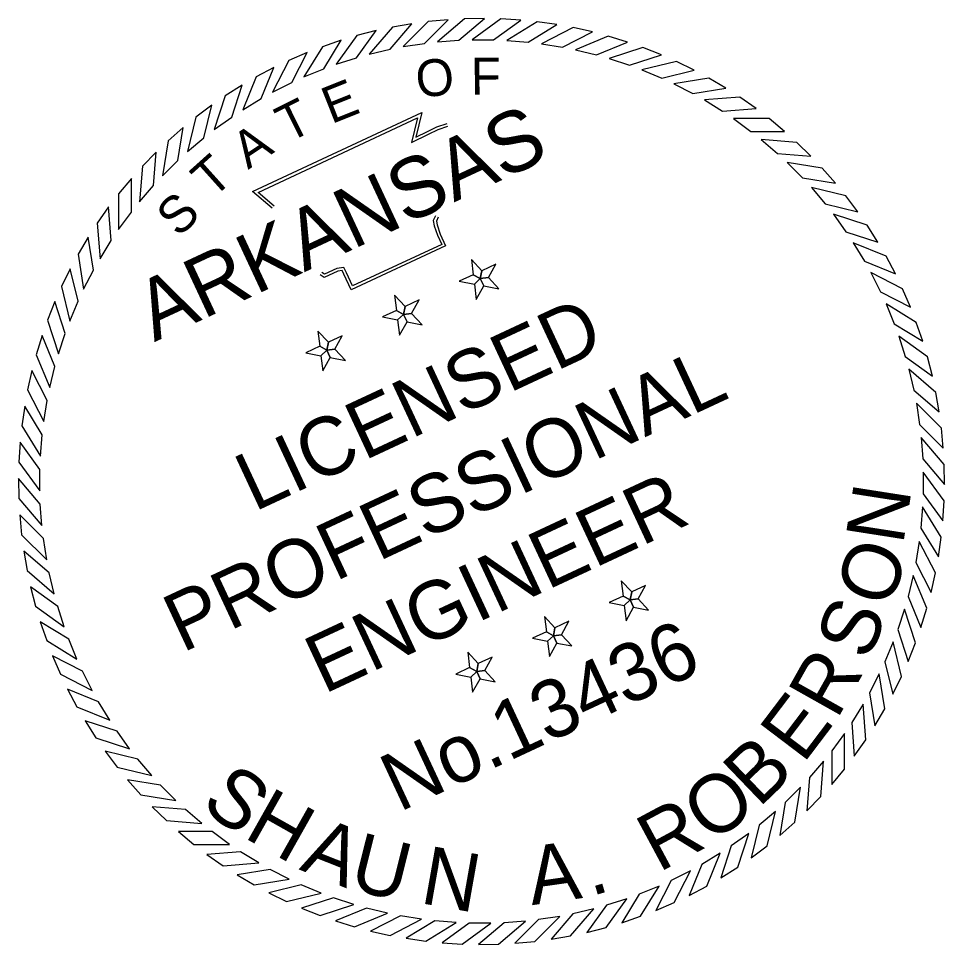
# Model space of a CAD drawing. Extents: x 756658 to 763719, y 1656413 to 1661090.
# Drawn here: x 759296.9 to 759535.5, y 1659245.9 to 1659484.6 of the extents above; entities that cross this region are included whole.
import ezdxf

# ---------------------------------------------------------------- set-up
doc = ezdxf.new("R2010")
doc.units = 0
doc.layers.add('G-ANNO-SYMB', color=7, linetype='Continuous')

msp = doc.modelspace()

# ---------------------------------------------------------------- linework, layer by layer
at = {"layer": 'G-ANNO-SYMB'}
for points in [[(759416.93, 1659484.58), (759411.8, 1659484.5), (759404.85, 1659478.56), (759410.37, 1659478.98)], [(759398.26, 1659483.23), (759393.2, 1659482.35), (759387.26, 1659475.4), (759392.66, 1659476.67)], [(759407.57, 1659484.27), (759402.46, 1659483.79), (759395.99, 1659477.33), (759401.47, 1659478.18)], [(759426.29, 1659484.16), (759421.17, 1659484.48), (759413.77, 1659479.1), (759419.31, 1659479.09)], [(759435.59, 1659483), (759430.51, 1659483.72), (759422.71, 1659478.94), (759428.24, 1659478.49)], [(759444.76, 1659481.11), (759439.76, 1659482.23), (759431.61, 1659478.08), (759437.08, 1659477.19)], [(759389.06, 1659481.46), (759384.09, 1659480.19), (759378.71, 1659472.79), (759383.99, 1659474.49)], [(759453.77, 1659478.51), (759448.86, 1659480.02), (759440.41, 1659476.52), (759445.8, 1659475.21)], [(759380.02, 1659478.98), (759375.17, 1659477.32), (759370.39, 1659469.52), (759375.52, 1659471.62)], [(759371.21, 1659475.79), (759366.5, 1659473.75), (759362.35, 1659465.6), (759367.3, 1659468.11)], [(759462.53, 1659475.21), (759457.76, 1659477.1), (759449.07, 1659474.28), (759454.33, 1659472.55)], [(759471.02, 1659471.24), (759466.41, 1659473.49), (759457.52, 1659471.36), (759462.63, 1659469.22)], [(759362.68, 1659471.92), (759358.14, 1659469.52), (759354.65, 1659461.07), (759359.38, 1659463.95)], [(759479.16, 1659466.61), (759474.75, 1659469.22), (759465.72, 1659467.79), (759470.65, 1659465.26)], [(759354.48, 1659467.39), (759350.14, 1659464.65), (759347.32, 1659455.95), (759351.81, 1659459.19)], [(759486.92, 1659461.35), (759482.72, 1659464.3), (759473.61, 1659463.59), (759478.32, 1659460.67)], [(759346.65, 1659462.24), (759342.55, 1659459.16), (759340.42, 1659450.27), (759344.64, 1659453.85)], [(759494.24, 1659455.5), (759490.29, 1659458.78), (759481.14, 1659458.78), (759485.62, 1659455.5)], [(759339.26, 1659456.48), (759335.41, 1659453.09), (759333.98, 1659444.06), (759337.91, 1659447.97)], [(759501.08, 1659449.1), (759497.4, 1659452.67), (759488.28, 1659453.39), (759492.48, 1659449.78)], [(759332.34, 1659450.17), (759328.77, 1659446.49), (759328.05, 1659437.37), (759331.66, 1659441.57)], [(759507.4, 1659442.18), (759504, 1659446.03), (759494.97, 1659447.46), (759498.88, 1659443.53)], [(759325.94, 1659443.33), (759322.67, 1659439.38), (759322.67, 1659430.23), (759325.94, 1659434.71)], [(759513.15, 1659434.79), (759510.07, 1659438.89), (759501.18, 1659441.03), (759504.76, 1659436.8)], [(759320.09, 1659436.01), (759317.14, 1659431.81), (759317.86, 1659422.69), (759320.77, 1659427.41)], [(759518.31, 1659426.97), (759515.56, 1659431.3), (759506.86, 1659434.13), (759510.1, 1659429.63)], [(759314.84, 1659428.25), (759312.22, 1659423.84), (759313.65, 1659414.8), (759316.19, 1659419.73)], [(759522.83, 1659418.76), (759520.43, 1659423.3), (759511.98, 1659426.8), (759514.86, 1659422.06)], [(759415.87, 1659417.55), (759416.27, 1659419.59), (759413.57, 1659422.49), (759414.05, 1659418.56)], [(759310.21, 1659420.11), (759307.95, 1659415.5), (759310.08, 1659406.61), (759312.22, 1659411.72)], [(759415.87, 1659417.55), (759417.94, 1659417.8), (759419.86, 1659421.27), (759416.27, 1659419.59)], [(759415.87, 1659417.55), (759414.05, 1659418.56), (759410.46, 1659416.88), (759414.35, 1659416.13)], [(759415.87, 1659417.55), (759416.75, 1659415.66), (759420.64, 1659414.9), (759417.94, 1659417.8)], [(759526.7, 1659410.23), (759524.66, 1659414.94), (759516.52, 1659419.09), (759519.02, 1659414.14)], [(759415.87, 1659417.55), (759414.35, 1659416.13), (759414.83, 1659412.19), (759416.75, 1659415.66)], [(759396.1, 1659408.33), (759396.49, 1659410.37), (759393.79, 1659413.27), (759394.28, 1659409.34)], [(759306.23, 1659411.62), (759304.34, 1659406.85), (759307.17, 1659398.16), (759308.9, 1659403.42)], [(759396.1, 1659408.33), (759398.17, 1659408.58), (759400.09, 1659412.05), (759396.49, 1659410.37)], [(759529.89, 1659401.42), (759528.23, 1659406.27), (759520.43, 1659411.05), (759522.53, 1659405.92)], [(759396.1, 1659408.33), (759394.28, 1659409.34), (759390.68, 1659407.66), (759394.57, 1659406.91)], [(759396.1, 1659408.33), (759394.57, 1659406.91), (759395.06, 1659402.97), (759396.98, 1659406.44)], [(759396.1, 1659408.33), (759396.98, 1659406.44), (759400.87, 1659405.68), (759398.17, 1659408.58)], [(759376.32, 1659399.11), (759376.72, 1659401.15), (759374.02, 1659404.05), (759374.5, 1659400.12)], [(759302.93, 1659402.85), (759301.42, 1659397.95), (759304.92, 1659389.5), (759306.23, 1659394.89)], [(759376.32, 1659399.11), (759378.39, 1659399.36), (759380.31, 1659402.83), (759376.72, 1659401.15)], [(759532.37, 1659392.39), (759531.1, 1659397.36), (759523.7, 1659402.73), (759525.4, 1659397.45)], [(759376.32, 1659399.11), (759374.5, 1659400.12), (759370.91, 1659398.44), (759374.8, 1659397.69)], [(759376.32, 1659399.11), (759374.8, 1659397.69), (759375.28, 1659393.75), (759377.2, 1659397.22)], [(759376.32, 1659399.11), (759377.2, 1659397.22), (759381.09, 1659396.46), (759378.39, 1659399.36)], [(759300.33, 1659393.85), (759299.21, 1659388.85), (759303.36, 1659380.7), (759304.25, 1659386.17)], [(759534.14, 1659383.19), (759533.26, 1659388.24), (759526.31, 1659394.18), (759527.59, 1659388.79)], [(759298.45, 1659384.68), (759297.72, 1659379.6), (759302.5, 1659371.8), (759302.95, 1659377.32)], [(759535.18, 1659373.88), (759534.7, 1659378.98), (759528.24, 1659385.45), (759529.09, 1659379.97)], [(759297.29, 1659375.38), (759296.96, 1659370.26), (759302.34, 1659362.86), (759302.36, 1659368.4)], [(759535.49, 1659364.51), (759535.42, 1659369.64), (759529.48, 1659376.6), (759529.89, 1659371.07)], [(759535.07, 1659355.15), (759535.39, 1659360.27), (759530.02, 1659367.67), (759530, 1659362.13)], [(759296.86, 1659366.02), (759296.94, 1659360.89), (759302.88, 1659353.94), (759302.46, 1659359.46)], [(759533.91, 1659345.86), (759534.63, 1659350.93), (759529.85, 1659358.73), (759529.4, 1659353.21)], [(759297.17, 1659356.66), (759297.65, 1659351.55), (759304.12, 1659345.08), (759303.27, 1659350.56)], [(759532.02, 1659336.68), (759533.14, 1659341.69), (759528.99, 1659349.83), (759528.11, 1659344.36)], [(759298.21, 1659347.35), (759299.09, 1659342.29), (759306.05, 1659336.35), (759304.77, 1659341.75)], [(759454.48, 1659334.74), (759454.88, 1659336.79), (759452.18, 1659339.69), (759452.66, 1659335.75)], [(759529.42, 1659327.68), (759530.93, 1659332.58), (759527.43, 1659341.03), (759526.12, 1659335.64)], [(759299.98, 1659338.15), (759301.25, 1659333.17), (759308.65, 1659327.8), (759306.96, 1659333.08)], [(759454.48, 1659334.74), (759456.55, 1659335), (759458.47, 1659338.46), (759454.88, 1659336.79)], [(759454.48, 1659334.74), (759452.66, 1659335.75), (759449.07, 1659334.08), (759452.96, 1659333.32)], [(759454.48, 1659334.74), (759452.96, 1659333.32), (759453.44, 1659329.39), (759455.36, 1659332.86)], [(759454.48, 1659334.74), (759455.36, 1659332.86), (759459.25, 1659332.1), (759456.55, 1659335)], [(759526.12, 1659318.91), (759528.01, 1659323.68), (759525.19, 1659332.38), (759523.46, 1659327.11)], [(759434.71, 1659325.52), (759435.11, 1659327.57), (759432.4, 1659330.47), (759432.89, 1659326.53)], [(759302.47, 1659329.11), (759304.13, 1659324.26), (759311.92, 1659319.48), (759309.82, 1659324.61)], [(759434.71, 1659325.52), (759436.78, 1659325.78), (759438.7, 1659329.24), (759435.11, 1659327.57)], [(759434.71, 1659325.52), (759432.89, 1659326.53), (759429.3, 1659324.86), (759433.19, 1659324.1)], [(759434.71, 1659325.52), (759433.19, 1659324.1), (759433.67, 1659320.17), (759435.59, 1659323.63)], [(759434.71, 1659325.52), (759435.59, 1659323.63), (759439.48, 1659322.88), (759436.78, 1659325.78)], [(759522.15, 1659310.43), (759524.41, 1659315.03), (759522.27, 1659323.92), (759520.13, 1659318.81)], [(759305.65, 1659320.3), (759307.69, 1659315.59), (759315.84, 1659311.44), (759313.34, 1659316.39)], [(759414.94, 1659316.3), (759415.33, 1659318.35), (759412.63, 1659321.25), (759413.11, 1659317.31)], [(759414.94, 1659316.3), (759417, 1659316.56), (759418.92, 1659320.02), (759415.33, 1659318.35)], [(759414.94, 1659316.3), (759413.11, 1659317.31), (759409.52, 1659315.64), (759413.41, 1659314.88)], [(759414.94, 1659316.3), (759413.41, 1659314.88), (759413.89, 1659310.95), (759415.82, 1659314.41)], [(759414.94, 1659316.3), (759415.82, 1659314.41), (759419.71, 1659313.66), (759417, 1659316.56)], [(759517.52, 1659302.28), (759520.13, 1659306.7), (759518.7, 1659315.73), (759516.17, 1659310.8)], [(759309.52, 1659311.77), (759311.92, 1659307.23), (759320.37, 1659303.73), (759317.49, 1659308.47)], [(759512.26, 1659294.52), (759515.22, 1659298.72), (759514.5, 1659307.84), (759511.59, 1659303.12)], [(759314.05, 1659303.57), (759316.8, 1659299.23), (759325.49, 1659296.41), (759322.25, 1659300.9)], [(759506.42, 1659287.2), (759509.69, 1659291.15), (759509.69, 1659300.3), (759506.42, 1659295.83)], [(759319.2, 1659295.74), (759322.28, 1659291.64), (759331.18, 1659289.5), (759327.59, 1659293.73)], [(759500.01, 1659280.36), (759503.59, 1659284.05), (759504.3, 1659293.16), (759500.69, 1659288.96)], [(759324.96, 1659288.35), (759328.35, 1659284.5), (759337.38, 1659283.07), (759333.48, 1659287)], [(759493.09, 1659274.05), (759496.94, 1659277.44), (759498.37, 1659286.47), (759494.44, 1659282.56)], [(759331.27, 1659281.43), (759334.96, 1659277.86), (759344.07, 1659277.14), (759339.87, 1659280.75)], [(759485.7, 1659268.29), (759489.8, 1659271.37), (759491.94, 1659280.26), (759487.71, 1659276.68)], [(759338.11, 1659275.03), (759342.07, 1659271.75), (759351.21, 1659271.75), (759346.74, 1659275.03)], [(759477.88, 1659263.14), (759482.21, 1659265.88), (759485.04, 1659274.58), (759480.54, 1659271.34)], [(759345.43, 1659269.18), (759349.63, 1659266.23), (759358.75, 1659266.95), (759354.03, 1659269.86)], [(759469.67, 1659258.61), (759474.21, 1659261.01), (759477.71, 1659269.46), (759472.97, 1659266.58)], [(759353.19, 1659263.93), (759357.61, 1659261.31), (759366.64, 1659262.74), (759361.71, 1659265.27)], [(759461.14, 1659254.74), (759465.85, 1659256.78), (759470, 1659264.93), (759465.06, 1659262.43)], [(759361.34, 1659259.3), (759365.94, 1659257.04), (759374.84, 1659259.17), (759369.72, 1659261.31)], [(759452.33, 1659251.56), (759457.19, 1659253.22), (759461.96, 1659261.01), (759456.84, 1659258.91)], [(759369.82, 1659255.32), (759374.59, 1659253.43), (759383.29, 1659256.26), (759378.02, 1659257.99)], [(759443.3, 1659249.07), (759448.27, 1659250.34), (759453.64, 1659257.74), (759448.37, 1659256.05)], [(759378.59, 1659252.02), (759383.49, 1659250.51), (759391.94, 1659254.01), (759386.56, 1659255.32)], [(759387.59, 1659249.42), (759392.6, 1659248.3), (759400.75, 1659252.45), (759395.27, 1659253.34)], [(759424.79, 1659246.26), (759429.9, 1659246.74), (759436.36, 1659253.2), (759430.88, 1659252.36)], [(759434.1, 1659247.3), (759439.15, 1659248.18), (759445.09, 1659255.13), (759439.7, 1659253.86)], [(759396.77, 1659247.54), (759401.85, 1659246.81), (759409.64, 1659251.59), (759404.12, 1659252.04)], [(759406.06, 1659246.38), (759411.18, 1659246.05), (759418.58, 1659251.43), (759413.04, 1659251.44)], [(759415.42, 1659245.95), (759420.55, 1659246.03), (759427.51, 1659251.97), (759421.98, 1659251.55)]]:
    msp.add_lwpolyline(points, close=True, dxfattribs=at)
for points in [[(759362.25, 1659435.67), (759357.19, 1659439.96), (759400.79, 1659460.32), (759399.28, 1659454.04), (759402.23, 1659455.46), (759404.69, 1659456.65), (759407.29, 1659457.53)], [(759362.75, 1659436.26), (759358.59, 1659439.77), (759399.68, 1659458.96), (759398.17, 1659452.66), (759402.56, 1659454.78), (759404.98, 1659455.94), (759407.53, 1659456.81)], [(759405, 1659433.35), (759404.54, 1659432.4), (759404.71, 1659431.38), (759405.52, 1659429), (759406.93, 1659425.99), (759382.58, 1659414.64), (759380.68, 1659418.71), (759380.26, 1659419.61), (759379.13, 1659419.45), (759375.67, 1659417.84), (759374.61, 1659418.49)], [(759404.32, 1659433.69), (759403.75, 1659432.51), (759403.97, 1659431.19), (759404.81, 1659428.72), (759405.92, 1659426.36), (759382.95, 1659415.65), (759381.37, 1659419.03), (759380.71, 1659420.44), (759378.91, 1659420.19), (759375.72, 1659418.7), (759375.02, 1659419.14)]]:
    msp.add_lwpolyline(points, dxfattribs=at)

# ---------------------------------------------------------------- texts
for s, height, rotation, p in [('O', 9.49, 6.2218, (759399.74, 1659464.11)), ('F', 9.49, 0.3628, (759413.45, 1659464.98)), ('E', 9.49, 21.672, (759377.47, 1659457.32)), ('T', 9.49, 26.4789, (759366.34, 1659452.45)), ('ARKANSAS', 15.494, 25, (759331.87, 1659401.16)), ('A', 9.49, 33.6788, (759356.03, 1659445.55)), ('T', 9.49, 41.9015, (759346.85, 1659437.95)), ('S', 9.49, 44.7726, (759338.2, 1659427.94)), ('LICENSED', 15, 25, (759357.6, 1659357.36)), ('PROFESSIONAL', 15.0001, 25, (759339.07, 1659321.04)), ('ENGINEER', 15, 25, (759375.57, 1659310.38)), ('N', 15, 81.1007, (759524.81, 1659348.76)), ('O', 15, 69.7757, (759521.08, 1659332.12)), ('S', 15, 68.4878, (759515.94, 1659318.75)), ('No.13436', 14.941, 25, (759394.97, 1659279.97)), ('R', 15, 60.6597, (759507.75, 1659303.68)), ('E', 15, 52.8315, (759499.07, 1659292.3)), ('B', 15, 43.885, (759487.63, 1659280.98)), ('S', 15, 323.1636, (759343.42, 1659281.47)), ('O', 15, 36.4296, (759475.34, 1659271.74)), ('H', 15, 330.619, (759354.58, 1659273.7)), ('R', 15, 28.2287, (759461.85, 1659264.38)), ('A', 15, 338.4472, (759369, 1659265.32)), ('U', 15, 345.9026, (759381.61, 1659260.41)), ('N', 15, 349.9326, (759400.03, 1659256.67)), ('A', 15, 8.0991, (759429.16, 1659256.06)), ('.', 15, 16.3, (759444.37, 1659258.33))]:
    msp.add_text(s, height=height, rotation=rotation, dxfattribs=at).set_placement(p)

doc.saveas('drawing.dxf')
